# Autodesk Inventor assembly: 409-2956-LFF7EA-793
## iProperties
Created: 2010-09
Part Number: 409-2956-LFF7EA-793
Document SubType Name: Weldment
Designer: S. Boerckel
Weld Material: Welded Aluminum-6061
Mass: 3209.93 g
Surface Area: 1265.7 cm^2
Volume: 408.746 cm^3
Density: 7.85311 g/cm^3
Description: INLET PIPE STAND
User Status: WELD
Material: WELDMENT
SMR: =<MATERIAL>
Author: S. Boerckel
Revision Number: A
